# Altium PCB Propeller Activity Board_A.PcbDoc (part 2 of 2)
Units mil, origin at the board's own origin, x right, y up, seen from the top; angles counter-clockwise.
Board outline 4000 x 3050 mil, 4 copper layers (Top Layer, INT1, INT2, Bottom Layer), stack 61.6 mil thick; 104 components, 104 nets, 469 pads, 175 vias.
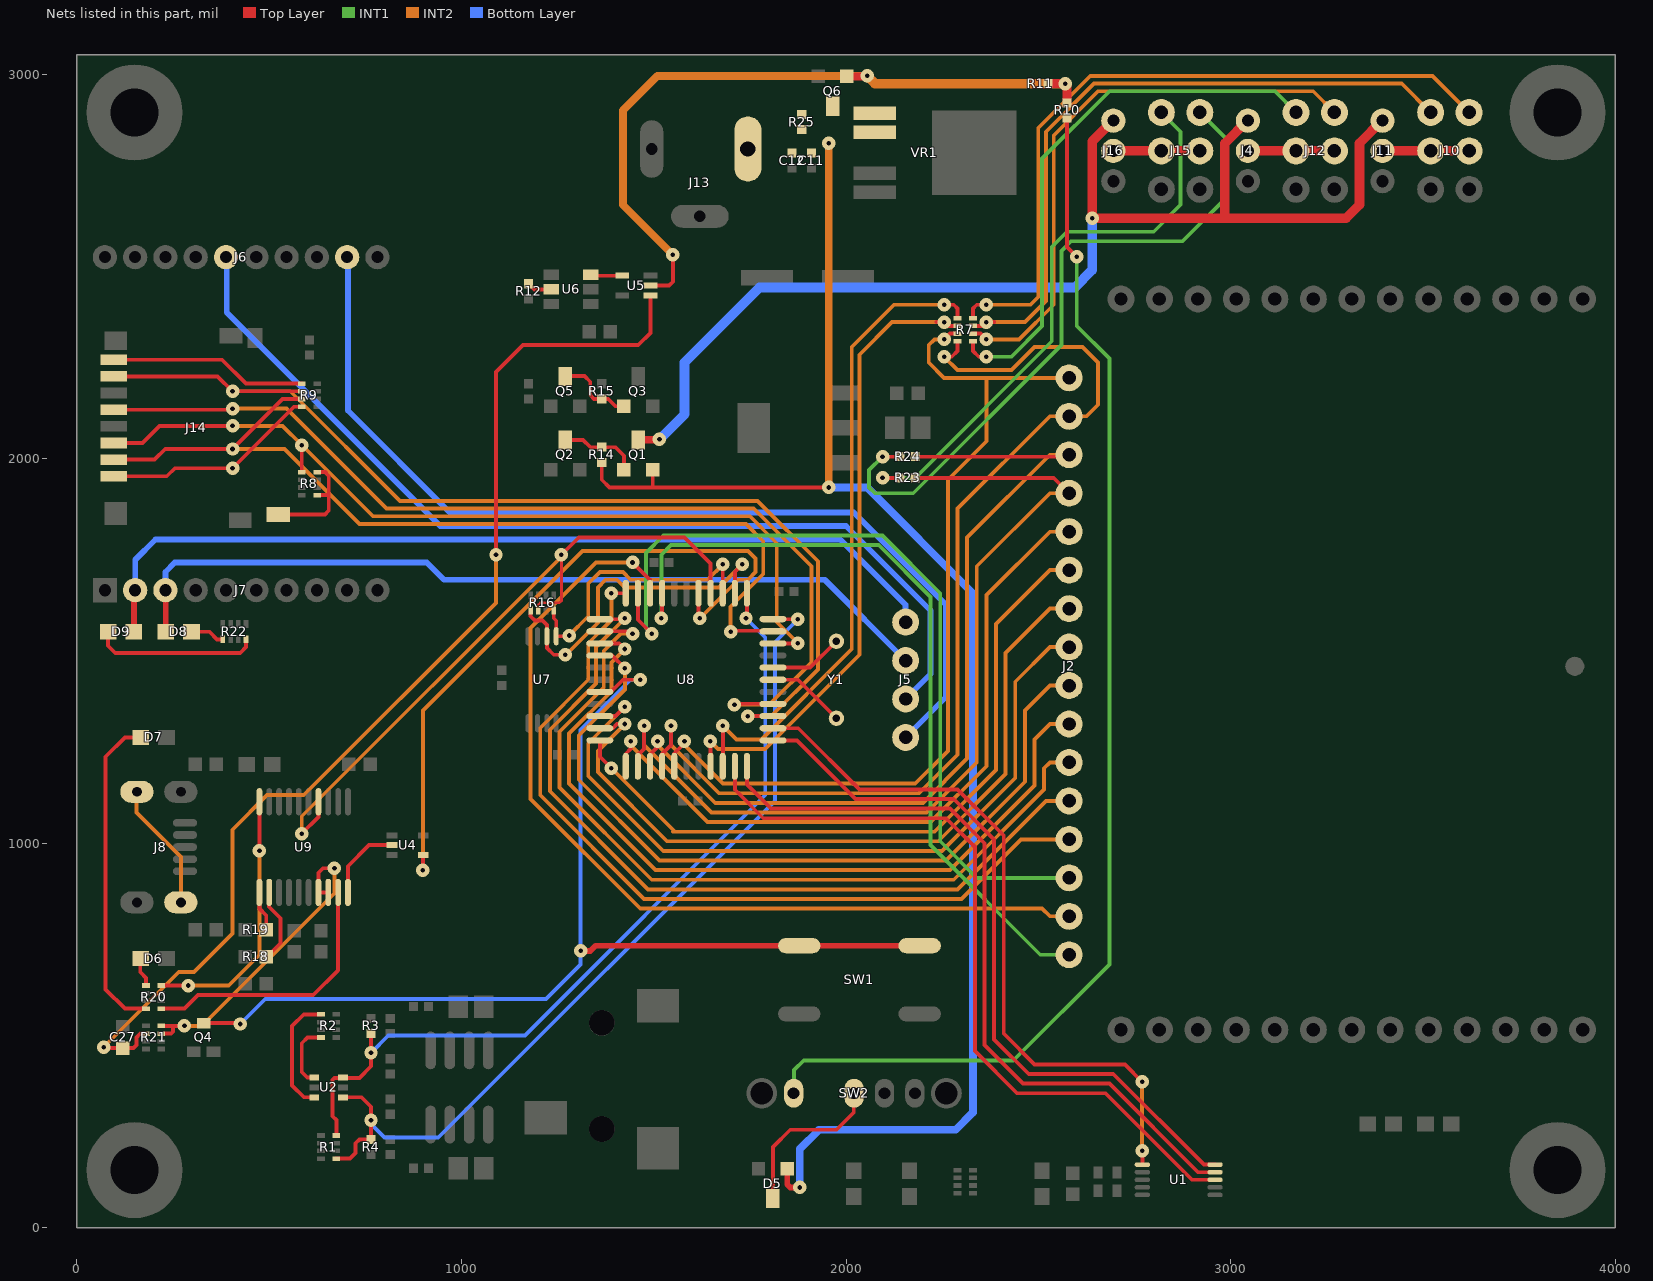
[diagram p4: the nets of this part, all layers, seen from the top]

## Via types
v1: diameter 35, hole 12, Top Layer to Bottom Layer, tented both sides, 168 vias
v2: diameter 50, hole 20, Top Layer to Bottom Layer, tented both sides, 7 vias

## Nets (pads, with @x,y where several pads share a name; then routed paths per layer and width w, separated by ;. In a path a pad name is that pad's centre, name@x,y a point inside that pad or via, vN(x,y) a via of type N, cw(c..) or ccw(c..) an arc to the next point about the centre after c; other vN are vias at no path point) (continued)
NetD5_3: D5.3 SW2.2 | length 431
  Top Layer w10: D5.3@1810,76.25 1810,210 1855,255 1975,255 2020,300 SW2.2@2020,350
NetD6_K: D6.K R20.5 | length 76.2
  Top Layer w10: D6.K@165,700 165,665 180,650 R20.5@180,630
NetD7_K: D7.K R20.8 | length 841.4
  Top Layer w10: D7.K@165,1275 125,1275 75,1225 75,620 125,570 R20.8@180,570
NetD8_1: D8.1 R22.1 | length 88.3
  Top Layer w10: D8.1@300,1550 345,1550 365,1530 R22.1@380,1530
NetD9_1: D9.1 R22.4 | length 428.9
  Top Layer w10: D9.1@81.54,1550 81.54,1513.46 100,1495 425,1495 440,1510 R22.4@440,1530
NetJ4_2: J4.2 J12.3 J12.4 | length 225
  Top Layer w25: J4.2@3045,2800 J12.4@3270,2800
NetJ10_1: J10.1 R7.7 | length 1759.8
  Top Layer w10: R7.7@2330,2345 2355,2345 v1(2365,2355) 2385,2355
  INT2 w10: v1(2365,2355) 2465,2355 2520,2410 2520,2850 2645,2975 3445,2975 J10.1@3520,2900
NetJ10_2: J10.2 R7.8 | length 1862.7
  Top Layer w10: R7.8@2330,2365 2330,2390 2340,2400 v1(2365,2400)
  INT2 w10: v1(2365,2400) 2480,2400 2500,2420 2500,2860 2635,2995 3525,2995 J10.2@3620,2900
NetJ10_3: J10.3 J10.4 J11.2 | length 225
  Top Layer w25: J11.2@3395,2800 J10.4@3620,2800
NetJ12_1: J12.1 R7.5 | length 1434.6
  Top Layer w10: R7.5@2330,2305 2330,2280 2345,2265 v1(2365,2265)
  INT1 w10: v1(2365,2265) 2430,2265 2510,2345 2510,2780 2685,2955 3115,2955 J12.1@3170,2900
NetJ12_2: J12.2 R7.6 | length 1493.9
  Top Layer w10: R7.6@2330,2325 2350,2325 v1(2365,2310)
  INT2 w10: v1(2365,2310) 2450,2310 2540,2400 2540,2840 2655,2955 3215,2955 J12.2@3270,2900
NetJ14_1: J14.1 R9.8 | length 563.4
  Top Layer w10: J14.1@96.61,1954.02 234.02,1954.02 255,1975 v1(405,1975) 565,2135 R9.8@585,2135
NetJ14_8: J14.8 R9.5 | length 514.1
  Top Layer w10: J14.8@96.61,2257.17 377.83,2257.17 440,2195 R9.5@585,2195
NetJ14_14: J14.14 R8.1 R8.4 | length 293.3
  Top Layer w10: J14.14@520,1855 J14.14@523.39,1855 645,1855 655,1865 655,1905 ; R8.1@625,1905 655,1905 ; R8.4@625,1965 645,1965 655,1955 655,1905
NetJ15_1: J15.1 R23.2 | length 1518.6
  Top Layer w10: v1(2095,1950) R23.2@2140.32,1950
  INT1 w10: v1(2095,1950) 2180,1950 2535,2305 2535,2550 2575,2590 2800,2590 2870,2660 2870,2850 J15.1@2820,2900
NetJ15_2: J15.2 R24.2 | length 1783.3
  Top Layer w10: v1(2095,2005) R24.2@2140.32,2005
  INT1 w10: v1(2095,2005) 2060,1970 2060,1925 2075,1910 2175,1910 2560,2295 2560,2540 2585,2565 2875,2565 2985,2675 2985,2835 J15.2@2920,2900
NetJ15_3: J15.3 J15.4 J16.2 | length 225
  Top Layer w25: J16.2@2695,2800 J15.4@2920,2800
NetQ1_1: Q1.1 Q2.3 R14.2 | length 207.1
  Top Layer w10: Q2.3@1270,2048.75 1316.25,2048.75 1335.32,2029.68 R14.2@1365,2029.68 1400.32,2029.68 1422.5,2007.5 Q1.1@1422.5,1971.25 ; Q1.1@1425,1970 Q1.1@1425,1971.25
NetQ3_1: Q3.1 Q5.3 R15.1 | length 205.6
  Top Layer w10: Q5.3@1270,2215 1320,2215 1335,2200 1335,2165 1344.68,2155.32 R15.1@1365,2155.32 1381.68,2155.32 1400.75,2136.25 Q3.1@1422.5,2136.25
NetQ6_1: Q6.1 R10.1 R11.2 U5.2 | length 1908.3
  Top Layer w10: U5.2@1491.61,2450 1540,2450 1550,2460 v1(1550,2530)
  Top Layer w20: Q6.1@2000,2993.75 v1@2055,2993.75
  Top Layer w23: R11.2@2528.62,2975 2575,2975 R10.1@2575,2925
  INT2 w20: v1(1550,2530) 1420,2660 1420,2905 1510,2995 v1(2055,2995)
  INT2 w25: v1(2055,2995) 2075,2975 v1(2570,2975)
NetQ6_3: Q6.3 R25.2 VR1.1
NetR2_5: R2.5 U2.6 | length 312.7
  Top Layer w10: U2.6@617.6,339.41 590.59,339.41 560,370 560,525 590,555 R2.5@635,555
NetR2_8: R2.8 U2.4 | length 169.8
  Top Layer w10: U2.4@617.6,390.59 599.41,390.59 585,405 585,480 600,495 R2.8@635,495
NetR12_2: R12.2 U6.5 | length 70.2
  Top Layer w10: R12.2@1175,2460 1175,2458.62 1175,2455 1190,2440 U6.5@1234,2440
NetR16_5: R16.5 U7.6 U8.35 | length 887.1
  Top Layer w10: R16.5@1180,1600 1180,1590 1191,1579 1211,1579 1222.2,1567.8 U7.6@1222.2,1538 1222.2,1507.8 1240,1490 v1(1270,1490) ; U8.35@1711,1650 1711,1706 v1(1730,1725)
  INT2 w10: v1(1270,1490) 1271.72,1490 1355,1573.28 1355,1665 1375,1685 1405,1685 1425,1665 1670,1665 v1(1730,1725)
NetR16_8: R16.8 U7.5 U8.36 | length 729
  Top Layer w10: R16.8@1240,1605 1240,1585 1246.61,1578.39 U7.5@1246.61,1538 1282,1538 v1(1280,1540) ; U8.36@1677.5,1652 U8.36@1679.5,1650 1679.5,1724.5 v1(1680,1725)
  INT2 w10: v1(1280,1540) 1330,1590 1330,1675 1360,1705 1420,1705 1440,1685 1640,1685 v1(1680,1725)
NetR18_1: R18.1 U9.12 | length 196.9
  Top Layer w10: R18.1@495,705 530,740 530,805 500,835 U9.12@500,875
NetR19_1: R19.1 U9.11 | length 104.5
  Top Layer w10: U9.11@474.84,872.2 474.84,830.16 492.5,812.5 R19.1@492.5,775
NetR20_1: R20.1 U9.19 | length 703.4
  Top Layer w10: R20.1@220,570 280,570 315,605 615,605 679.57,669.57 U9.19@679.57,872.2
NetR20_4: R20.4 U9.10 | length 695.9
  Top Layer w10: R20.4@220,630 v1(290,630) ; v1@474.84,980 U9.10@474.84,1107.8 ; v1@475,970 v1(475,980)
  INT2 w10: v1(290,630) 395,630 475,710 v1(475,980)
NetR21_3: R21.3 R21.4 U9.17 U9.18 | length 826.4
  Top Layer w10: R21.3@220,505 245,505 250,510 250,525 ; R21.4@220,525 250,525 ; v1(280,525) 250,525 ; U9.18@652.2,872.2 U9.17@628.39,872.2 628.39,923.39 640,935 v1(670,935)
  INT2 w10: v1(280,525) 325,525 670,870 v1(670,935)
NetU4_2: U4.2 U9.20 | length 205.2
  Top Layer w10: U9.20@705.16,872.2 705.16,940.16 760,995 U4.2@819.65,995
NetU5_4: U5.4 U6.3 | length 83.4
  Top Layer w10: U6.3@1336,2478 1338.41,2475.59 U5.4@1418.39,2475.59
NetU8_28: U8.28 Y1.1 | length 206.4
  Top Layer w10: U8.28@1810,1425 1875,1425 Y1.1@1975,1325
NetU8_29: U8.29 Y1.2 | length 193.4
  Top Layer w10: U8.29@1810,1456.5 1906.5,1456.5 Y1.2@1975,1525
P0: J2.16 U8.41 | length 2120.2
  Top Layer w10: v1(1520,1585) 1522,1587 U8.41@1522,1650
  INT1 w10: v1(1520,1585) 1520,1750 1545,1775 2085,1775 2220,1640 2220,995 2505,710 J2.16@2580,710
P1: J2.15 U8.42 | length 2405.6
  Top Layer w10: v1(1445,1730) 1490.5,1684.5 U8.42@1490.5,1650
  INT2 w10: v1(1445,1730) 1350,1730 1180,1560 1180,1115 1465,830 2510,830 2530,810 J2.15@2580,810
P2: J2.14 U8.43 | length 2201.2
  Top Layer w10: U8.43@1459,1650 1459,1581 v1(1495,1545)
  INT1 w10: v1(1495,1545) 1480,1560 1480,1755 1525,1800 2095,1800 2245,1650 2245,1005 2340,910 J2.14@2580,910
P3: J2.13 U8.44 | length 2190.2
  Top Layer w10: v1(1390,1650) U8.44@1427.5,1650
  INT2 w10: v1(1390,1650) 1390,1580 1330,1520 1330,1425 1205,1300 1205,1125 1475,855 2300,855 2455,1010 J2.13@2580,1010
P4: J2.12 U8.1 | length 2144.2
  Top Layer w10: U8.1@1360,1582.5 v1@1422.5,1582.5
  INT2 w10: v1(1425,1585) 1350,1510 1350,1415 1230,1295 1230,1135 1485,880 2290,880 2520,1110 J2.12@2580,1110
P5: J2.11 U8.2 | length 2158.2
  Top Layer w10: U8.2@1360,1551 v1@1439,1551
  INT2 w10: v1(1445,1545) 1415,1545 1370,1500 1370,1405 1255,1290 1255,1145 1495,905 2280,905 2515,1140 2515,1195 2530,1210 J2.11@2580,1210
P6: J2.10 U8.3 | length 2102
  Top Layer w10: U8.3@1360,1519.5 1410.5,1519.5 v1(1425,1505)
  INT2 w10: v1(1425,1505) 1390,1470 1390,1395 1280,1285 1280,1155 1505,930 2270,930 2490,1150 2490,1270 2530,1310 J2.10@2580,1310
P7: J2.9 U8.4 | length 2077.2
  Top Layer w10: U8.4@1360,1488 1392,1488 v1(1425,1455)
  INT2 w10: v1(1425,1455) 1425,1400 1305,1280 1305,1165 1515,955 2260,955 2465,1160 2465,1345 2530,1410 J2.9@2580,1410
P8: J2.8 U8.9 | length 1991.2
  Top Layer w10: U8.9@1360,1330.5 1400.5,1330.5 v1(1425,1355)
  INT2 w10: v1(1425,1355) 1330,1260 1330,1175 1525,980 2250,980 2440,1170 2440,1420 2530,1510 J2.8@2580,1510
P9: J2.7 U8.10 | length 1958.2
  Top Layer w10: U8.10@1360,1299 1394,1299 1405,1310 v1(1425,1310)
  INT2 w10: v1(1425,1310) 1355,1240 1355,1185 1535,1005 2240,1005 2415,1180 2415,1495 2530,1610 J2.7@2580,1610
P10: J2.6 U8.11 | length 1852.5
  Top Layer w10: U8.11@1360,1267.5 1360,1225 v1(1390,1195)
  INT2 w10: v1(1390,1195) 1555,1030 ; 1550,1030 2230,1030 2390,1190 2390,1570 2530,1710 J2.6@2580,1710
P11: J2.5 U8.12 | length 1876.4
  Top Layer w10: U8.12@1427.5,1200 1427.5,1232.5 1440,1245 v1(1440,1265)
  INT2 w10: v1(1440,1265) 1440,1255 1640,1055 2220,1055 2365,1200 2365,1645 2530,1810 J2.5@2580,1810
P12: J2.4 R23.1 U8.13 | length 2398.1
  Top Layer w10: U8.13@1459,1200 1459,1229 1475,1245 v1(1475,1305) ; R23.1@2179.68,1950 2540,1950 J2.4@2579.68,1910.32
  INT2 w10: v1(1475,1305) 1475,1255 1650,1080 2210,1080 2340,1210 2340,1720 2530,1910 J2.4@2580,1910
P13: J2.3 R24.1 U8.14 | length 2328.8
  Top Layer w10: U8.14@1490.5,1200 1490.5,1230.5 1510,1250 v1(1510,1265) ; R24.1@2180,2005 2574.37,2005 J2.3@2579.68,2010.32
  INT2 w10: v1(1510,1265) 1510,1255 1660,1105 2200,1105 2315,1220 2315,1795 2530,2010 J2.3@2580,2010
P14: J2.2 R7.4 U8.15 | length 2751.7
  Top Layer w10: U8.15@1522,1200 1522,1232 1545,1255 v1(1545,1305) ; v1(2255,2265) 2275,2265 2290,2280 R7.4@2290,2305
  INT2 w10: v1(1545,1305) 1545,1255 1670,1130 2190,1130 2290,1230 2290,1870 2530,2110 J2.2@2580,2110 2625,2110 2655,2140 2655,2250 2615,2290 2490,2290 2430,2230 2290,2230 v1(2255,2265)
P15: J2.1 R7.3 U8.16 | length 2373
  Top Layer w10: U8.16@1553.5,1200 1553.5,1233.5 1580,1260 v1(1580,1265) ; v1(2255,2310) 2270,2325 R7.3@2290,2325
  INT2 w10: v1(1580,1265) 1580,1255 1680,1155 2180,1155 2265,1240 2265,1945 2365,2045 2365,2210 ; v1(2255,2310) 2230,2310 2215,2295 2215,2250 2255,2210 J2.1@2580,2210
P16: R7.2 U8.19 | length 1656.1
  Top Layer w10: U8.19@1648,1200 v1@1648,1264.5 ; 2235,2355 v1(2255,2355) 2265,2345 R7.2@2290,2345
  INT2 w10: v1(1647.5,1265) 1667.5,1245 1790,1245 2035,1490 2035,2270 2120,2355 v1(2255,2355)
P17: R7.1 U8.20 | length 1686.5
  Top Layer w10: U8.20@1679.5,1200 1680,1200.5 1680,1304 v1@1679.5,1304.5 ; v1(2255,2400) 2280,2400 2290,2390 R7.1@2290,2365
  INT2 w10: v1(1680,1305) 1715,1270 1780,1270 2015,1505 2015,2290 2125,2400 v1(2255,2400)
P18: U1.8 U8.21 | length 2040
  Top Layer w10: U8.21@1711,1200 1711,1139 1785,1065 2260,1065 2335,990 2335,460 2445,350 2675,350 2900,125 U1.8@2959.5,125
P19: U1.9 U8.22 | length 1989.5
  Top Layer w10: U8.22@1742.5,1200 1742.5,1152.5 1805,1090 2270,1090 2360,1000 2360,475 2460,375 2685,375 2915.3,144.7 U1.9@2959.5,144.7
P20: U1.10 U8.23 | length 1911
  Top Layer w10: U8.23@1810,1267.5 1872.5,1267.5 2025,1115 2280,1115 2385,1010 2385,490 2475,400 2695,400 2930.6,164.4 U1.10@2959.5,164.4
P21: U1.1 U8.24 | length 1857.9
  Top Layer w10: U8.24@1810,1299 1876,1299 2035,1140 2290,1140 2410,1020 2410,505 2490,425 2725,425 v1(2770,380) ; U1.1@2770.5,164.4 v1@2770.5,200
  INT2 w10: v1(2770,200) v1(2770,380)
P22: J14.7 R9.6 U8.25 | length 2787.6
  Top Layer w10: J14.7@96.61,2213.86 366.14,2213.86 v1(405,2175) R9.6@585,2175 ; v1@1745.5,1330.5 U8.25@1810,1330.5
  INT2 w10: v1(405,2175) 555,2175 840,1890 1770,1890 1927,1733 1927,1452 1805,1330 v1(1745,1330)
P23: J14.5 U8.26 | length 2574.4
  Top Layer w10: J14.5@96.61,2127.24 v1@402.24,2127.24 ; v1@1712,1362 1712.5,1362.5 1809.5,1362.5 U8.26@1810,1362
  INT2 w10: v1(405,2130) 545,2130 805,1870 1760,1870 1910,1720 1910,1470 1800,1360 v1(1710,1360)
P24: J14.3 R8.5 U8.31 | length 2285.9
  Top Layer w10: J14.3@96.61,2040.63 170.63,2040.63 215,2085 v1(405,2085) ; R8.5@585,1965 v1(585,2035) ; U8.31@1810,1519.5 v1@1875,1519.5
  INT2 w10: v1(405,2085) 535,2085 v1(585,2035) 770,1850 1750,1850 1820,1780 1820,1575 v1(1875,1520)
P25: J14.2 R9.7 U8.32 | length 2413.6
  Top Layer w10: J14.2@96.61,1997.32 202.32,1997.32 230,2025 v1(405,2025) 535,2155 R9.7@585,2155 ; v1@1701,1551 1702.5,1552.5 1808.5,1552.5 U8.32@1810,1551
  INT2 w10: v1(405,2025) 540,2025 735,1830 1740,1830 1785,1785 1785,1700 1700,1615 v1(1700,1550)
P26: R1.1 R4.2 U2.1 U8.33 | length 2294.6
  Top Layer w10: R1.1@675,180 710,180 725,195 725,220 734.68,229.68 R4.2@765,229.68 v1(765,280) 765,315 740.59,339.41 U2.1@692.4,339.41 ; U8.33@1810,1582.5 v1(1875,1582.5)
  Bottom Layer w10: v1@765,275 760,275 800,235 940,235 1815,1110 1815,1522.5 v1(1875,1582.5)
P27: R1.4 R3.2 U2.3 U8.34 | length 2194.7
  Top Layer w10: R1.4@675,240 675,280 665,290 665,385 670,390 735,390 765,420 v1(765,455) R3.2@765,505.32 ; v1@1742.5,1587.5 U8.34@1742.5,1650
  Bottom Layer w10: v1(765,455) 810,500 1165,500 1790,1125 1790,1535 v1(1740,1585)
P\W\R\_\E\N\: R10.2 SW2.1 | length 3239.5
  Top Layer w10: R10.2@2575,2885 2575,2550 v1(2600,2525)
  INT1 w10: SW2.1@1865,350 1865,410 1890,435 2435,435 2685,685 2685,2260 2600,2345 v1(2600,2525)
"PROPELLER R\E\S\E\T\ (R\S\T\)": Q4.3 SW1.1 U8.7 | length 2869.2
  Top Layer w10: Q4.3@330,532.4 422.6,532.4 v1(425,530) ; U8.7@1360,1393.5 1388.5,1393.5 1420,1425 v1(1465,1425)
  Top Layer w15: v1(1310,720) 1335,720 1348.58,733.58 SW1.1@1878.5,733.58 SW1.1@2191.5,733.58
  Bottom Layer w10: v1(425,530) 490,595 1220,595 1310,685 v1(1310,720) 1310,1295 1440,1425 v1(1465,1425)
"SERIAL/USB RX": U4.4 U8.38 | length 1792.4
  Top Layer w10: v1@900.35,930.35 U4.4@900.35,969.41 ; v1@1616.5,1586.5 U8.38@1616.5,1650
  INT2 w10: v1(900,930) 900,1345 1315,1760 1745,1760 1765,1740 1765,1705 1745,1685 1720,1685 v1(1620,1585)
"SERIAL/USB TX": R16.6 U8.37 U9.4 | length 1818.4
  Top Layer w6: R16.6@1200,1605 1200,1620 1205,1625 1255,1625 1260,1630
  Top Layer w8: 1260,1630 v1@1260,1745
  Top Layer w10: v1(585,1025) 628.39,1068.39 U9.4@628.39,1107.8 ; v1@1255,1750 v1@1260,1745 ; v1(1260,1750) 1305,1795 1580,1795 1648,1727 U8.37@1648,1650
  INT2 w10: v1(585,1025) 585,1070 1260,1745 v1(1260,1750)
SHEILD: J8.7 J8.8 | length 336.6
  INT2 w10: J8.8@155,1135 155,1080 270.59,964.41 J8.7@270.59,846.3
U\S\B\_\P\W\R\_\E\N\: C27.1 R21.6 U5.1 | length 2943.9
  Top Layer w10: v1@75.32,475.32 v1(70,470) 72.5,467.5 C27.1@120,467.5 147.5,467.5 155,475 155,495 165,505 R21.6@180,505 ; v1(1090,1750) 1090,2225 1160,2295 1460,2295 1491.61,2326.61 U5.1@1491.61,2424.41
  INT2 w10: v1(70,470) 265,665 305,665 405,765 405,1035 495,1125 590,1125 1090,1625 v1(1090,1750)
VIN: C11.1 C12.1 D5.1 J13.+ Q1.2 R14.1 R25.1 VR1.2 | length 4090.7
  Top Layer w10: R14.1@1365,1990 1365,1945 1385,1925 1495,1925 ; Q1.2@1497.5,1971.25 1497.5,1927.5 1495,1925 ; v1(1955,1925) 1495,1925
  Top Layer w15: D5.1@1847.5,153.75 1847.5,112.5 1855,105 v1(1880,105)
  INT2 w20: v1(1955,1925) v1(1955,2820)
  Bottom Layer w20: v1(1880,105) 1880,205 1930,255 2285,255 2330,300 2330,1650 2055,1925 v1(1955,1925)
VIN_AUX: J4.1 J11.1 J16.1 Q1.3 | length 3087.1
  Top Layer w20: Q1.3@1460,2048.75 v1@1513.75,2048.75
  Top Layer w25: J16.1@2695,2880 2640,2825 v1(2640,2625) 3300,2625 3335,2660 3335,2820 J11.1@3395,2880 ; 2985,2625 2985,2820 J4.1@3045,2880
  Bottom Layer w25: v1(1515,2050) 1580,2115 1580,2250 1775,2445 2595,2445 2640,2490 v1(2640,2625)
"XBEE C\T\S\ (C\T\S\)": J5.4 J6.9 | length 2552.3
  Bottom Layer w15: J6.9@702.98,2523.83 705,2521.81 705,2125 970,1860 2020,1860 2260,1620 2260,1380 J5.4@2155,1275
"XBEE DATA IN (DI)": D8.2 J5.2 J7.3 | length 2198.6
  Top Layer w15: J7.3@230,1660 231.54,1658.46 D8.2@231.54,1550
  Bottom Layer w15: J7.3@230.54,1657.83 230.54,1705.54 255,1730 910,1730 955,1685 1945,1685 J5.2@2155,1475
"XBEE DATA OUT (DO)": D9.2 J5.1 J7.2 | length 2332.3
  Top Layer w15: D9.2@148.46,1550 148.46,1653.46 J7.2@155,1660
  Bottom Layer w15: J7.2@151.8,1657.83 151.8,1736.8 205,1790 1985,1790 2155,1620 J5.1@2155,1575
"XBEE R\T\S\ (R\T\S\)": J5.3 J6.5 | length 2558.8
  Bottom Layer w15: J6.5@385,2523.83 J6.5@385,2530 ; J6.5@388.02,2523.83 390,2521.85 390,2380 945,1825 2000,1825 2220,1605 2220,1440 J5.3@2155,1375
pads on no net: J6.1 J6.2 J6.3 J6.4 J6.6 J6.7 J6.8 J6.10 J7.4 J7.5 J7.6 J7.7 J7.8 J7.9 J8.2 J8.6 J8.9 J9.4 J9.5 J13.S J14.9 J14.10 J14.11 J14.12 R1.2 R1.3 R1.6 R1.7 R2.2 R2.3 R2.6 R2.7 R8.2 R8.3 R8.6 R8.7 R16.2 R16.7 R17.2 R17.3 R17.6 R17.7 R20.2 R20.3 R20.6 R20.7 R21.2 R21.7 R22.2 R22.3 R22.6 R22.7 SW1.2@1878.5,556.42 SW2.3 SW2.5 SW2.6 U6.4 U7.3 U9.2 U9.5 U9.7 U9.8 U9.9 VR1.5

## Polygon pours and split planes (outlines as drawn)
5V on Top Layer "Top-Layer-5V" (solid, pour order 10): 3375.5,2457.5 3375.5,2367.5 2670.5,2367.5 2645.5,2392.5 2645.5,2467.5 2620.5,2492.5 2120.5,2492.5 2095.5,2517.5 2095.5,2657.5 1940.5,2657.5 1940.5,2152.5 2095.5,2152.5 2095.5,2407.5 2120.5,2432.5 2555.5,2432.5 2580.5,2407.5 2580.5,2287.5 2605.5,2262.5 3950.5,2262.5 3950.5,2457.5
GND on Top Layer "Top-VSS" (solid, remove dead copper, pour order 15): 25,3025 3975,3025 3975,25 25,25
GND on Bottom Layer "Bottom-VSS" (solid, remove dead copper, pour order 20): 25,3025 3975,3025 3975,25 25,25
3.3V on INT1 "INT1-3.3V" (solid, remove dead copper, pour order 17): 25,3025 3975,3025 3975,25 25,25
GND on INT2 "INT2-VSS" (solid, remove dead copper, pour order 18): 25,3025 3975,3025 3975,25 25,25

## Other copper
Top Layer:
  rectangle net NetQ6_3: 1870,2885 2130,2940
  region net 5V: 1995,2605 1995,2765 1940,2765 1940,2605
  region net GND: 2155,3000 2155,2505 2495,2505 2495,3000
  pour cut-out: 2150,2195 2170,2195 2170,2145 2150,2145
  region net VIN: 1710,2865 2130,2865 2130,2785 1845,2785 1820,2760 1710,2760
  region net 5V: 1940,2765 2130,2765 2130,2725 1940,2725
  region net 3.3V: 1650,2200 1865,2200 1865,2125 2130,2125 2130,2035 1865,2035 1865,1950 1650,1950
  pour cut-out: 3845,1510 3945,1510 3945,1410 3845,1410
  pour cut-out: 2040,2125 2040,2150 1935,2150 1935,2125
  pour cut-out: 2660,2950 3670,2950 3670,2650 2660,2650
INT1:
  region net GND: 2155,3000 2155,2505 2495,2505 2495,3000
INT2:
  rectangle net GND: 2155,2505 2440,2955
  rectangle net 3.3V: 1650,1950 1865,2200
Bottom Layer:
  rectangle net GND: 2155,2510 2495,3000
  rectangle net 3.3V: 1650,1950 1865,2200
  pour cut-out: 2655,2950 3670,2950 3670,2650 2655,2650

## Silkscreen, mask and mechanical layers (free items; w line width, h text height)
Top Overlay:
  drawing of 85 lines, arcs and shapes, not listed
  text "P12" at 2744,2985 h75
  text "P13" at 2885,2985 h75
  text "P14" at 3097,2985 h75
  text "P15" at 3235,2985 h75
  text "P16" at 3443,2985 h75
  text "P17" at 3586,2985 h75
  text "6-9 VDC" at 813.9,2950.12 h100
  text "VIN" at 2641,2932 h70
  text "VIN" at 2990,2932 h70
  text "VIN" at 3341,2932 h70
  text "-" at 1154.77,2921.27 h39.88 r180
  text "+" at 995.23,2881.39 h53.18
  text "V+" at 3682,2773 h75
  text "GND" at 3682,2673 h75
  text "XBee" at 43,2641 h90
  text "5V" at 2656,2625 h70
  text "5V" at 3006,2625 h70
  text "5V" at 3356,2625 h70
  text "CTS" at 637,2583 h75
  text "RTS" at 324,2582 h75
  text "3.3V" at 2933,2535 h90
  text "5V" at 3620,2535 h90
  text "microSD" at 608,2352 h90
  text "DO-" at 695,2251 h75
  text "P22" at 820,2251 h75
  text "P15" at 2377,2181 h90
  text "CLK-" at 656,2151 h75
  text "P23" at 820,2151 h75
  text "P14" at 2377,2081 h90
  text "CD," at 609,2051 h75
  text "DI-" at 729,2051 h75
  text "P24" at 820,2051 h75
  text "P13" at 2377,1981 h90
  text "CS-" at 701,1951 h75
  text "P25" at 820,1951 h75
  text "P12" at 2377,1881 h90
  text "P11" at 2377,1781 h90
  text "3.3V" at 21,1758 h75
  text "GND" at 711,1758 h75
  text "P10" at 2377,1681 h90
  text "XBee" at 2101,1659 h90
  text "P9" at 2422,1581 h90
  text "DO" at 2224,1552 h75
  text "EEPROM" at 798,1488 h90
  text "P8" at 2422,1481 h90
  text "DO" at 69,1453 h75
  text "DI" at 236,1453 h75
  text "DI" at 2224,1451 h75
  text "SDA-P29" at 798,1419 h75
  text "P7" at 2422,1381 h90
  text "v" at 214,1355 h75 r90
  text "SCL-P28" at 798,1350 h75
  text "RTS" at 2224,1349 h75
  text "Serial" at 233,1327 h90
  text "P6" at 2422,1281 h90
  text "CTS" at 2224,1250 h75
  text "P5" at 2422,1181 h90
  text "Tx>P31" at 20,1177 h75
  text "P4" at 2422,1081 h90
  text "TM" at 1876,1020 h75
  text "P3" at 2422,981 h90
  text "Propeller" at 1101,945 h200
  text "P2" at 2422,881 h90
  text "Activity Board" at 1063,795 h200
  text "P1" at 2422,781 h90
  text "Rx<P30" at 20,752 h75
  text "P0" at 2422,681 h90
  text "D/A" at 929,647 h90
  text "L" at 1508,645 h75
  text "RST" at 1738,619 h90
  text "P26" at 1509,461 h75
  text "0" at 3394,394 h85
  text "1" at 3512,394 h85
  text "0" at 3598,394 h85
  text "1" at 3696,394 h85
  text "2" at 3796,394 h85
  text "3" at 3898,394 h85
  text "R" at 1178,353 h75
  text "GND" at 2929,337 h90
  text "D/A" at 3406,321 h85
  text "/D" at 3694,321 h85
  text "A" at 3698,321 h85
  text "A" at 2796,208 h90
  text "/D" at 2857,208 h90
  text "PWR" at 1590,195 h90
  text "0" at 1864,195 h90
  text "1" at 2001,195 h90
  text "2" at 2141,195 h90
  text "CS-P21" at 3035,195 h75
  text "P27" at 3489,176 h75
  text "P26" at 3338,175 h75
  text "P27" at 1110,170 h75
  text "SCL-P20" at 2993,136 h75
  text "DO-P19" at 3029,78 h75
  text "DI-P18" at 3062,20 h75
Bottom Overlay:
  lines w15: 310.06,254.88 ccw(c525,250) 314.86,204.57 ; 310.06,2804.88 ccw(c525,2800) 314.86,2754.57 ; 311.99,279.18 cw(c525,250) 324.69,328.1 ; 311.99,2829.18 cw(c525,2800) 324.69,2878.1 ; 321.35,181.07 ccw(c525,250) 343.07,135.43 ; 321.35,2731.07 ccw(c525,2800) 343.07,2685.43 ; 334.82,350.27 cw(c525,250) 363.48,391.9 ; 334.82,2900.27 cw(c525,2800) 363.48,2941.9 ; 357.21,115.57 ccw(c525,250) 393.22,80.12 ; 357.21,2665.57 ccw(c525,2800) 393.22,2630.12 ; 380.58,409.27 cw(c525,250) 421.75,438.59 ; 380.58,2959.27 cw(c525,2800) 421.75,2988.59 ; 413.3,66.29 ccw(c525,250) 459.28,45.29 ; 413.3,2616.29 ccw(c525,2800) 459.28,2595.29 ; 443.76,449.06 cw(c525,250) 492.48,462.53 ; 443.76,2999.06 cw(c525,2800) 492.48,3012.53 ; 482.87,39.17 ccw(c525,250) 533.25,35.16 ; 482.87,2589.17 ccw(c525,2800) 533.25,2585.16 ; 516.75,464.84 cw(c525,250) 567.13,460.83 ; 516.75,3014.84 cw(c525,2800) 567.13,3010.83 ; 557.52,37.47 ccw(c525,250) 606.24,50.94 ; 557.52,2587.47 ccw(c525,2800) 606.24,2600.94 ; 590.72,454.71 cw(c525,250) 636.7,433.71 ; 590.72,3004.71 cw(c525,2800) 636.7,2983.71 ; 628.25,61.41 ccw(c525,250) 669.42,90.73 ; 628.25,2611.41 ccw(c525,2800) 669.42,2640.73 ; 656.77,419.88 cw(c525,250) 692.79,384.43 ; 656.77,2969.88 cw(c525,2800) 692.79,2934.43 ; 686.52,108.1 ccw(c525,250) 715.18,149.73 ; 686.52,2658.1 ccw(c525,2800) 715.18,2699.73 ; 706.93,364.57 cw(c525,250) 728.65,318.93 ; 706.93,2914.57 cw(c525,2800) 728.65,2868.93 ; 725.31,171.9 ccw(c525,250) 738.01,220.82 ; 725.31,2721.9 ccw(c525,2800) 738.01,2770.82 ; 735.14,295.43 cw(c525,250) 739.94,245.12 ; 735.14,2845.43 cw(c525,2800) 739.94,2795.12 ; 3260.06,254.88 ccw(c3475,250) 3264.86,204.57 ; 3261.99,279.18 cw(c3475,250) 3274.69,328.1 ; 3271.35,181.07 ccw(c3475,250) 3293.07,135.43 ; 3284.82,350.27 cw(c3475,250) 3313.48,391.9 ; 3307.21,115.57 ccw(c3475,250) 3343.22,80.12 ; 3330.58,409.27 cw(c3475,250) 3371.75,438.59 ; 3363.3,66.29 ccw(c3475,250) 3409.28,45.29 ; 3393.76,449.06 cw(c3475,250) 3442.48,462.53 ; 3432.87,39.17 ccw(c3475,250) 3483.25,35.16 ; 3466.75,464.84 cw(c3475,250) 3517.13,460.83 ; 3507.52,37.47 ccw(c3475,250) 3556.24,50.94 ; 3536.83,2159.76 ccw(c3751.78,2154.88) 3541.63,2109.45 ; 3538.76,2184.06 cw(c3751.78,2154.88) 3551.46,2232.98 ; 3540.72,454.71 cw(c3475,250) 3586.7,433.71 ; 3548.12,2085.95 ccw(c3751.78,2154.88) 3569.84,2040.32 ; 3561.59,2255.16 cw(c3751.78,2154.88) 3590.25,2296.78 ; 3578.25,61.41 ccw(c3475,250) 3619.38,90.69 ; 3583.98,2020.46 ccw(c3751.78,2154.88) 3620,1985 ; 3606.77,419.88 cw(c3475,250) 3642.79,384.43 ; 3607.35,2314.16 cw(c3751.77,2154.88) 3648.53,2343.47 ; 3636.52,108.1 ccw(c3475,250) 3665.18,149.73 ; 3640.08,1971.17 ccw(c3751.78,2154.88) 3686.05,1950.18 ; 3656.93,364.57 cw(c3475,250) 3678.65,318.93 ; 3670.54,2353.95 cw(c3751.78,2154.88) 3719.25,2367.41 ; 3675.31,171.9 ccw(c3475,250) 3688.01,220.82 ; 3685.14,295.43 cw(c3475,250) 3689.94,245.12 ; 3709.65,1944.05 ccw(c3751.77,2154.88) 3760.03,1940.04 ; 3743.52,2369.72 cw(c3751.78,2154.88) 3793.9,2365.72 ; 3784.3,1942.36 ccw(c3751.78,2154.88) 3833.01,1955.82 ; 3817.5,2359.59 cw(c3751.77,2154.88) 3863.47,2338.59 ; 3855.02,1966.3 ccw(c3751.78,2154.88) 3896.19,1995.61 ; 3883.55,2324.77 cw(c3751.77,2154.88) 3919.57,2289.31 ; 3913.3,2012.98 ccw(c3751.77,2154.88) 3941.96,2054.61 ; 3933.71,2269.45 cw(c3751.78,2154.88) 3955.43,2223.82 ; 3952.09,2076.78 ccw(c3751.78,2154.88) 3964.79,2125.7 ; 3961.92,2200.32 cw(c3751.78,2154.88) 3966.72,2150.01
  lines w15.04: 2723.43,1724.78 2723.43,1769.89 2791.1,1769.89 2791.1,1724.78 ; 2723.43,1792.44 2791.1,1792.44 2723.43,1860.11 2791.1,1860.11 ; 2723.43,1882.67 2791.1,1882.67 ; 2858.77,1724.78 2926.44,1792.44 ; 2858.77,1882.67 2926.44,1815 ; 2948.99,1792.44 3016.66,1724.78 ; 2948.99,1815 3016.66,1882.67 ; 3039.22,1747.33 3039.22,1882.67 3174.55,1747.33 ; 3039.22,1815 3106.88,1815 ; 3129.44,1702.22 3264.78,1702.22 3264.78,1837.56 ; 3197.11,1747.33 3332.44,1747.33 3332.44,1882.67 ; 3355,1747.33 3355,1882.67 3490.34,1747.33 ; 3355,1815 3422.67,1815 ; 3445.22,1747.33 3445.22,1792.44 3467.78,1815 ; 3580.56,1747.33 3580.56,1882.67 3467.78,1882.67 3445.22,1860.11 3445.22,1837.56 3467.78,1815 ; 3580.56,1815 3467.78,1815 ; 3605.56,1747.33 3605.56,1882.67 3740.89,1747.33 ; 3605.56,1815 3671.49,1815 ; 3831.12,1747.33 3831.12,1882.67 3718.34,1882.67 3695.78,1860.11 3695.78,1837.56 3718.34,1815 3831.12,1815
  text "32910" at 1235.28,2830 h150
  text "Rev A" at 1225,2700 h150
  text "TM" at 1410,2485 h100
  text "Propeller" at 2180,2390 h200
  text "Activity Board" at 2215,2240 h200
  text "www.parallax.com" at 3825,1500 h135
  text "learn.parallax.com" at 3825,1350 h135
  text "Downloads & Resources" at 2190,1135 h135
  text "Rocklin, CA - USA" at 3825,1050 h135
  text "(" at 749,1045 h100
  text "(" at 1389,1045 h100
  text "www.parallax.com   search 32910" at 2190,1030 h125
  text "916 624 8333" at 3825,900 h135
  text "Online Tutorials" at 2190,840 h135
  text "learn.parallax.com/PropellerAB" at 2190,735 h125
  text "Tech Support" at 2190,540 h135
  text "support@parallax.com" at 2190,435 h125
Bottom Solder:
  drawing of 930 lines, arcs and shapes, not listed
  text "open source" at 2965.8,145 h80
  text "hardware" at 2920,85 h80
Mechanical 1:
  circle w10: c1300,2400 r5
  circle w10: c1465,2430 r5
  circle w10: c1410,1600 r5
  circle w10: c1070,425 r5
  circle w10: c670,337.5 r5
  text "PROPELLER ACTIVITY BOARD REV A" at 342,3148 h125
  text "J13" at 1245,2770 h60
  text "ASSY NOTES" at 1560,-305 h75
  text "1) Solder parts per IPC-A-610E." at 1360,-405 h50
  text "2) Finished product to be clean of" at 1360,-505 h50
  text "all flux and foreign material." at 1360,-605 h50
Mechanical 2:
  the board outline again, w10
Mechanical 19:
  the board outline again, w5

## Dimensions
0,0 to 0,3050 on Mechanical 1
0,0 to 4000,0 on Mechanical 1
